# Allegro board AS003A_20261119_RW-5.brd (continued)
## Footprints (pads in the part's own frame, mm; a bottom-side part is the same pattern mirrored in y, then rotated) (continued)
PG_VG93K_PF_DPS32_G8D429
  rect 1.778x1.778 hole 0.711: A1(20.32,3.81) A3(15.24,3.81) A5(10.16,3.81) A7(5.08,3.81) A9(0,3.81) A11(-5.08,3.81) A13(-10.16,3.81) A15(-15.24,3.81) B2(17.78,1.27) B4(12.7,1.27) B6(7.62,1.27) B8(2.54,1.27) B10(-2.54,1.27) B12(-7.62,1.27) B14(-12.7,1.27) B16(-17.78,1.27) C1(20.32,-1.27) C3(15.24,-1.27) C5(10.16,-1.27) C7(5.08,-1.27) C9(0,-1.27) C11(-5.08,-1.27) C13(-10.16,-1.27) C15(-15.24,-1.27) D2(17.78,-3.81) D4(12.7,-3.81) D6(7.62,-3.81) D8(2.54,-3.81) D10(-2.54,-3.81) D12(-7.62,-3.81) D14(-12.7,-3.81) D16(-17.78,-3.81)
  round 1.524 hole 0.711: A2(17.78,3.81) A4(12.7,3.81) A6(7.62,3.81) A8(2.54,3.81) A10(-2.54,3.81) A12(-7.62,3.81) A14(-12.7,3.81) A16(-17.78,3.81) A17(-20.32,3.81) B1(20.32,1.27) B3(15.24,1.27) B5(10.16,1.27) B7(5.08,1.27) B9(0,1.27) B11(-5.08,1.27) B13(-10.16,1.27) B15(-15.24,1.27) B17(-20.32,1.27) C2(17.78,-1.27) C4(12.7,-1.27) C6(7.62,-1.27) C8(2.54,-1.27) C10(-2.54,-1.27) C12(-7.62,-1.27) C14(-12.7,-1.27) C16(-17.78,-1.27) C17(-20.32,-1.27) D1(20.32,-3.81) D3(15.24,-3.81) D5(10.16,-3.81) D7(5.08,-3.81) D9(0,-3.81) D11(-5.08,-3.81) D13(-10.16,-3.81) D15(-15.24,-3.81) D17(-20.32,-3.81)
PG_VG93K_PF_UHC4_G8D230_A34_V2
  round 1.524 hole 0.711: A1(20.325,2.625) A2(18.575,2.625) A3(16.825,2.625) A4(15.075,2.625) B1(20.325,0.875) B2(18.575,0.875) B3(16.825,0.875) B4(15.075,0.875) C1(20.325,-0.875) C2(18.575,-0.875) C3(16.825,-0.875) C4(15.075,-0.875) D1(20.325,-2.625) D2(18.575,-2.625) D3(16.825,-2.625) D4(15.075,-2.625)
  rect 5.6x8.3 smd: G3(10.85,0) G4(-18.95,0)
  round 1.27 hole 0.711: G3_1(13.15,3.5) G3_2(10.85,3.5) G3_3(8.55,3.5) G3_4(12,1.75) G3_5(9.7,1.75) G3_6(13.15,0) G3_7(10.85,0) G3_8(8.55,0) G3_9(12,-1.75) G3_10(9.7,-1.75) G3_11(13.15,-3.5) G3_12(10.85,-3.5) G3_13(8.55,-3.5) G4_1(-16.65,3.5) G4_2(-18.95,3.5) G4_3(-21.25,3.5) G4_4(-17.8,1.75) G4_5(-20.1,1.75) G4_6(-16.65,0) G4_7(-18.95,0) G4_8(-21.25,0) G4_9(-17.8,-1.75) G4_10(-20.1,-1.75) G4_11(-16.65,-3.5) G4_12(-18.95,-3.5) G4_13(-21.25,-3.5) P3_1(6.55,3.5) P3_2(3.35,3.5) P3_3(0.15,3.5) P3_4(-3.05,3.5) P3_5(6.55,0) P3_6(3.35,0) P3_7(0.15,0) P3_8(-3.05,0) P3_9(6.55,-3.5) P3_10(3.35,-3.5) P3_11(0.15,-3.5) P3_12(-3.05,-3.5) P3_13(4.95,1.75) P3_14(1.75,1.75) P3_15(-1.45,1.75) P3_16(4.95,-1.75) P3_17(1.75,-1.75) P3_18(-1.45,-1.75) P4_1(-5.05,3.5) P4_2(-8.25,3.5) P4_3(-11.45,3.5) P4_4(-14.65,3.5) P4_5(-5.05,0) P4_6(-8.25,0) P4_7(-11.45,0) P4_8(-14.65,0) P4_9(-5.05,-3.5) P4_10(-8.25,-3.5) P4_11(-11.45,-3.5) P4_12(-14.65,-3.5) P4_13(-6.65,1.75) P4_14(-9.85,1.75) P4_15(-13.05,1.75) P4_16(-6.65,-1.75) P4_17(-9.85,-1.75) P4_18(-13.05,-1.75)
  rect 10.6x8.3 smd: P3(1.75,0) P4(-9.85,0)
PG_VG93K_PF_UHC4_G8D430_B12_V2
  round 1.524 hole 0.711: A1(20.325,2.625) A2(18.575,2.625) A3(16.825,2.625) A4(15.075,2.625) B1(20.325,0.875) B2(18.575,0.875) B3(16.825,0.875) B4(15.075,0.875) C1(20.325,-0.875) C2(18.575,-0.875) C3(16.825,-0.875) C4(15.075,-0.875) D1(20.325,-2.625) D2(18.575,-2.625) D3(16.825,-2.625) D4(15.075,-2.625)
  rect 5.6x8.3 smd: G1(-18.95,0) G2(10.85,0)
  round 1.27 hole 0.711: G1_1(-16.65,3.5) G1_2(-18.95,3.5) G1_3(-21.25,3.5) G1_4(-17.8,1.75) G1_5(-20.1,1.75) G1_6(-16.65,0) G1_7(-18.95,0) G1_8(-21.25,0) G1_9(-17.8,-1.75) G1_10(-20.1,-1.75) G1_11(-16.65,-3.5) G1_12(-18.95,-3.5) G1_13(-21.25,-3.5) G2_1(13.15,3.5) G2_2(10.85,3.5) G2_3(8.55,3.5) G2_4(12,1.75) G2_5(9.7,1.75) G2_6(13.15,0) G2_7(10.85,0) G2_8(8.55,0) G2_9(12,-1.75) G2_10(9.7,-1.75) G2_11(13.15,-3.5) G2_12(10.85,-3.5) G2_13(8.55,-3.5) P1_1(-5.05,3.5) P1_2(-8.25,3.5) P1_3(-11.45,3.5) P1_4(-14.65,3.5) P1_5(-5.05,0) P1_6(-8.25,0) P1_7(-11.45,0) P1_8(-14.65,0) P1_9(-5.05,-3.5) P1_10(-8.25,-3.5) P1_11(-11.45,-3.5) P1_12(-14.65,-3.5) P1_13(-6.65,1.75) P1_14(-9.85,1.75) P1_15(-13.05,1.75) P1_16(-6.65,-1.75) P1_17(-9.85,-1.75) P1_18(-13.05,-1.75) P2_1(6.55,3.5) P2_2(3.35,3.5) P2_3(0.15,3.5) P2_4(-3.05,3.5) P2_5(6.55,0) P2_6(3.35,0) P2_7(0.15,0) P2_8(-3.05,0) P2_9(6.55,-3.5) P2_10(3.35,-3.5) P2_11(0.15,-3.5) P2_12(-3.05,-3.5) P2_13(4.95,1.75) P2_14(1.75,1.75) P2_15(-1.45,1.75) P2_16(4.95,-1.75) P2_17(1.75,-1.75) P2_18(-1.45,-1.75)
  rect 10.6x8.3 smd: P1(-9.85,0) P2(1.75,0)
R0201
  rect 0.305x0.356 smd: 1(-0.3,0) 2(0.3,0)
R0402
  custom 0.15x0.15 smd: 1(-0.5,0) 2(0.5,0)
R0402_UNBGA_V2
  rect 0.508x0.508 smd: 1(-0.425,0) 2(0.425,0)
R0603
  rect 0.889x0.889 smd: 1(-0.85,0) 2(0.85,0)
R0805
  rect 1.118x1.372 smd: 1(-0.95,0) 2(0.95,0)
R1206
  rect 1.321x1.829 smd: 1(-1.25,0) 2(1.25,0)
RL_712D_5V_V2
  round 1.397 hole 1.041: 1(1.493,-2.055) 2(2.416,-0.785) 3(2.416,0.785) 4(1.493,2.055) 6(-1.493,2.055) 7(-2.416,0.785) 8(-2.416,-0.785) 9(-1.493,-2.055)
RL_COTO2911_5V_RLPIN
  rect 1.88x1.88 hole 1.372: 1(17.78,0)
  round 0.051 smd: 2(15.24,0)
  round 1.88 hole 1.372: 3(2.54,0) 4(0,0) 5(0,-2.54) 6(2.54,-2.54) 7(15.24,-2.54) 8(17.78,-2.54)
RL_NECUA2_5V_V3
  rect 1.626x1.626 hole 1.041: 1(3.6,1.6)
  round 1.626 hole 1.041: 2(0.4,1.6) 3(-1.8,1.6) 4(-4,1.6) 5(-4,-1.6) 6(-1.8,-1.6) 7(0.4,-1.6) 8(3.6,-1.6)
RL_SGRF303_5V
  oval 3.429x0.559 smd rot 54: 1(2.344,-3.226) 6(-2.344,3.226)
  oval 3.429x0.559 smd rot 18: 2(3.793,-1.232) 7(-3.793,1.232)
  oval 3.429x0.559 smd rot 162: 3(3.793,1.232) 8(-3.793,-1.232)
  oval 3.429x0.559 smd rot 126: 4(2.344,3.226) 9(-2.344,-3.226)
  custom 2.5x2.5 smd: G1(0,0)
  round 1.397 hole 1.041: G2(0,-2.54) G3(0,2.54)
SK_BGA1024P_0P8MM_WW_71117890
  round 0.508 hole 1.61 unplated: (-17.5,17.5) (-17.5,-17.5) (17.5,17.5) (17.5,-17.5)
  round 0.6 smd: A1(-12.4,12.4) A2(-11.6,12.4) A3(-10.8,12.4) A4(-10,12.4) A5(-9.2,12.4) A6(-8.4,12.4) A7(-7.6,12.4) A8(-6.8,12.4) A9(-6,12.4) A10(-5.2,12.4) A11(-4.4,12.4) A12(-3.6,12.4) A13(-2.8,12.4) A14(-2,12.4) A15(-1.2,12.4) A16(-0.4,12.4) A17(0.4,12.4) A18(1.2,12.4) A19(2,12.4) A20(2.8,12.4) A21(3.6,12.4) A22(4.4,12.4) A23(5.2,12.4) A24(6,12.4) A25(6.8,12.4) A26(7.6,12.4) A27(8.4,12.4) A28(9.2,12.4) A29(10,12.4) A30(10.8,12.4) A31(11.6,12.4) A32(12.4,12.4) AA1(-12.4,-3.6) AA2(-11.6,-3.6) AA3(-10.8,-3.6) AA4(-10,-3.6) AA5(-9.2,-3.6) AA6(-8.4,-3.6) AA7(-7.6,-3.6) AA8(-6.8,-3.6) AA9(-6,-3.6) AA10(-5.2,-3.6) AA11(-4.4,-3.6) AA12(-3.6,-3.6) AA13(-2.8,-3.6) AA14(-2,-3.6) AA15(-1.2,-3.6) AA16(-0.4,-3.6) AA17(0.4,-3.6) AA18(1.2,-3.6) AA19(2,-3.6) AA20(2.8,-3.6) AA21(3.6,-3.6) AA22(4.4,-3.6) AA23(5.2,-3.6) AA24(6,-3.6) AA25(6.8,-3.6) AA26(7.6,-3.6) AA27(8.4,-3.6) AA28(9.2,-3.6) AA29(10,-3.6) AA30(10.8,-3.6) AA31(11.6,-3.6) AA32(12.4,-3.6) AB1(-12.4,-4.4) AB2(-11.6,-4.4) AB3(-10.8,-4.4) AB4(-10,-4.4) AB5(-9.2,-4.4) AB6(-8.4,-4.4) AB7(-7.6,-4.4) AB8(-6.8,-4.4) AB9(-6,-4.4) AB10(-5.2,-4.4) AB11(-4.4,-4.4) AB12(-3.6,-4.4) AB13(-2.8,-4.4) AB14(-2,-4.4) AB15(-1.2,-4.4) AB16(-0.4,-4.4) AB17(0.4,-4.4) AB18(1.2,-4.4) AB19(2,-4.4) AB20(2.8,-4.4) AB21(3.6,-4.4) AB22(4.4,-4.4) AB23(5.2,-4.4) AB24(6,-4.4) AB25(6.8,-4.4) AB26(7.6,-4.4) AB27(8.4,-4.4) AB28(9.2,-4.4) AB29(10,-4.4) AB30(10.8,-4.4) AB31(11.6,-4.4) AB32(12.4,-4.4) AC1(-12.4,-5.2) AC2(-11.6,-5.2) AC3(-10.8,-5.2) AC4(-10,-5.2) AC5(-9.2,-5.2) AC6(-8.4,-5.2) AC7(-7.6,-5.2) AC8(-6.8,-5.2) AC9(-6,-5.2) AC10(-5.2,-5.2) AC11(-4.4,-5.2) AC12(-3.6,-5.2) AC13(-2.8,-5.2) AC14(-2,-5.2) AC15(-1.2,-5.2) AC16(-0.4,-5.2) AC17(0.4,-5.2) AC18(1.2,-5.2) AC19(2,-5.2) AC20(2.8,-5.2) AC21(3.6,-5.2) AC22(4.4,-5.2) AC23(5.2,-5.2) AC24(6,-5.2) AC25(6.8,-5.2) AC26(7.6,-5.2) AC27(8.4,-5.2) AC28(9.2,-5.2) AC29(10,-5.2) AC30(10.8,-5.2) AC31(11.6,-5.2) AC32(12.4,-5.2) AD1(-12.4,-6) AD2(-11.6,-6) AD3(-10.8,-6) AD4(-10,-6) AD5(-9.2,-6) AD6(-8.4,-6) AD7(-7.6,-6) AD8(-6.8,-6) AD9(-6,-6) AD10(-5.2,-6) AD11(-4.4,-6) AD12(-3.6,-6) AD13(-2.8,-6) AD14(-2,-6) AD15(-1.2,-6) AD16(-0.4,-6) AD17(0.4,-6) AD18(1.2,-6) AD19(2,-6) AD20(2.8,-6) AD21(3.6,-6) AD22(4.4,-6) AD23(5.2,-6) AD24(6,-6) AD25(6.8,-6) AD26(7.6,-6) AD27(8.4,-6) AD28(9.2,-6) AD29(10,-6) AD30(10.8,-6) AD31(11.6,-6) AD32(12.4,-6) AE1(-12.4,-6.8) AE2(-11.6,-6.8) AE3(-10.8,-6.8) AE4(-10,-6.8) AE5(-9.2,-6.8) AE6(-8.4,-6.8) AE7(-7.6,-6.8) AE8(-6.8,-6.8) AE9(-6,-6.8) AE10(-5.2,-6.8) AE11(-4.4,-6.8) AE12(-3.6,-6.8) AE13(-2.8,-6.8) AE14(-2,-6.8) AE15(-1.2,-6.8) AE16(-0.4,-6.8) AE17(0.4,-6.8) AE18(1.2,-6.8) AE19(2,-6.8) AE20(2.8,-6.8) AE21(3.6,-6.8) AE22(4.4,-6.8) AE23(5.2,-6.8) AE24(6,-6.8) AE25(6.8,-6.8) AE26(7.6,-6.8) AE27(8.4,-6.8) AE28(9.2,-6.8) AE29(10,-6.8) AE30(10.8,-6.8) AE31(11.6,-6.8) AE32(12.4,-6.8) AF1(-12.4,-7.6) AF2(-11.6,-7.6) AF3(-10.8,-7.6) AF4(-10,-7.6) AF5(-9.2,-7.6) AF6(-8.4,-7.6) AF7(-7.6,-7.6) AF8(-6.8,-7.6) AF9(-6,-7.6) AF10(-5.2,-7.6) AF11(-4.4,-7.6) AF12(-3.6,-7.6) AF13(-2.8,-7.6) AF14(-2,-7.6) AF15(-1.2,-7.6) AF16(-0.4,-7.6) AF17(0.4,-7.6) AF18(1.2,-7.6) AF19(2,-7.6) AF20(2.8,-7.6) AF21(3.6,-7.6) AF22(4.4,-7.6) AF23(5.2,-7.6) AF24(6,-7.6) AF25(6.8,-7.6) AF26(7.6,-7.6) AF27(8.4,-7.6) AF28(9.2,-7.6) AF29(10,-7.6) AF30(10.8,-7.6) AF31(11.6,-7.6) AF32(12.4,-7.6) AG1(-12.4,-8.4) AG2(-11.6,-8.4) AG3(-10.8,-8.4) AG4(-10,-8.4) AG5(-9.2,-8.4) AG6(-8.4,-8.4) AG7(-7.6,-8.4) AG8(-6.8,-8.4) AG9(-6,-8.4) AG10(-5.2,-8.4) AG11(-4.4,-8.4) AG12(-3.6,-8.4) AG13(-2.8,-8.4) AG14(-2,-8.4) AG15(-1.2,-8.4) AG16(-0.4,-8.4) AG17(0.4,-8.4) AG18(1.2,-8.4) AG19(2,-8.4) AG20(2.8,-8.4) AG21(3.6,-8.4) AG22(4.4,-8.4) AG23(5.2,-8.4) AG24(6,-8.4) AG25(6.8,-8.4) AG26(7.6,-8.4) AG27(8.4,-8.4) AG28(9.2,-8.4) AG29(10,-8.4) AG30(10.8,-8.4) AG31(11.6,-8.4) AG32(12.4,-8.4) AH1(-12.4,-9.2) AH2(-11.6,-9.2) AH3(-10.8,-9.2) AH4(-10,-9.2) AH5(-9.2,-9.2) AH6(-8.4,-9.2) AH7(-7.6,-9.2) AH8(-6.8,-9.2) AH9(-6,-9.2) AH10(-5.2,-9.2) AH11(-4.4,-9.2) AH12(-3.6,-9.2) AH13(-2.8,-9.2) AH14(-2,-9.2) AH15(-1.2,-9.2) AH16(-0.4,-9.2) AH17(0.4,-9.2) AH18(1.2,-9.2) AH19(2,-9.2) AH20(2.8,-9.2) AH21(3.6,-9.2) AH22(4.4,-9.2) AH23(5.2,-9.2) AH24(6,-9.2) AH25(6.8,-9.2) AH26(7.6,-9.2) AH27(8.4,-9.2) AH28(9.2,-9.2) AH29(10,-9.2) AH30(10.8,-9.2) AH31(11.6,-9.2) AH32(12.4,-9.2) AJ1(-12.4,-10) AJ2(-11.6,-10) AJ3(-10.8,-10) AJ4(-10,-10) AJ5(-9.2,-10) AJ6(-8.4,-10) AJ7(-7.6,-10) AJ8(-6.8,-10) AJ9(-6,-10) AJ10(-5.2,-10) AJ11(-4.4,-10) AJ12(-3.6,-10) AJ13(-2.8,-10) AJ14(-2,-10) AJ15(-1.2,-10) AJ16(-0.4,-10) AJ17(0.4,-10) AJ18(1.2,-10) AJ19(2,-10) AJ20(2.8,-10) AJ21(3.6,-10) AJ22(4.4,-10) AJ23(5.2,-10) AJ24(6,-10) AJ25(6.8,-10) AJ26(7.6,-10) AJ27(8.4,-10) AJ28(9.2,-10) AJ29(10,-10) AJ30(10.8,-10) AJ31(11.6,-10) AJ32(12.4,-10) AK1(-12.4,-10.8) AK2(-11.6,-10.8) AK3(-10.8,-10.8) AK4(-10,-10.8) AK5(-9.2,-10.8) AK6(-8.4,-10.8) AK7(-7.6,-10.8) AK8(-6.8,-10.8) AK9(-6,-10.8) AK10(-5.2,-10.8) AK11(-4.4,-10.8) AK12(-3.6,-10.8) AK13(-2.8,-10.8) AK14(-2,-10.8) AK15(-1.2,-10.8) AK16(-0.4,-10.8) AK17(0.4,-10.8) AK18(1.2,-10.8) AK19(2,-10.8) AK20(2.8,-10.8) AK21(3.6,-10.8) AK22(4.4,-10.8) AK23(5.2,-10.8) AK24(6,-10.8) AK25(6.8,-10.8) AK26(7.6,-10.8) AK27(8.4,-10.8) AK28(9.2,-10.8) AK29(10,-10.8) AK30(10.8,-10.8) AK31(11.6,-10.8) AK32(12.4,-10.8) AL1(-12.4,-11.6) AL2(-11.6,-11.6) AL3(-10.8,-11.6) AL4(-10,-11.6) AL5(-9.2,-11.6) AL6(-8.4,-11.6) AL7(-7.6,-11.6) AL8(-6.8,-11.6) AL9(-6,-11.6) AL10(-5.2,-11.6) AL11(-4.4,-11.6) AL12(-3.6,-11.6) AL13(-2.8,-11.6) AL14(-2,-11.6) AL15(-1.2,-11.6) AL16(-0.4,-11.6) AL17(0.4,-11.6) AL18(1.2,-11.6) AL19(2,-11.6) AL20(2.8,-11.6) AL21(3.6,-11.6) AL22(4.4,-11.6) AL23(5.2,-11.6) AL24(6,-11.6) AL25(6.8,-11.6) AL26(7.6,-11.6) AL27(8.4,-11.6) AL28(9.2,-11.6) AL29(10,-11.6) AL30(10.8,-11.6) AL31(11.6,-11.6) AL32(12.4,-11.6) AM1(-12.4,-12.4) AM2(-11.6,-12.4) AM3(-10.8,-12.4) AM4(-10,-12.4) AM5(-9.2,-12.4) AM6(-8.4,-12.4) AM7(-7.6,-12.4) AM8(-6.8,-12.4) AM9(-6,-12.4) AM10(-5.2,-12.4) AM11(-4.4,-12.4) AM12(-3.6,-12.4) AM13(-2.8,-12.4) AM14(-2,-12.4) AM15(-1.2,-12.4) AM16(-0.4,-12.4) AM17(0.4,-12.4) AM18(1.2,-12.4) AM19(2,-12.4) AM20(2.8,-12.4) AM21(3.6,-12.4) AM22(4.4,-12.4) AM23(5.2,-12.4) AM24(6,-12.4) AM25(6.8,-12.4) AM26(7.6,-12.4) AM27(8.4,-12.4) AM28(9.2,-12.4) AM29(10,-12.4) AM30(10.8,-12.4) AM31(11.6,-12.4) AM32(12.4,-12.4) B1(-12.4,11.6) B2(-11.6,11.6) B3(-10.8,11.6) B4(-10,11.6) B5(-9.2,11.6) B6(-8.4,11.6) B7(-7.6,11.6) B8(-6.8,11.6) B9(-6,11.6) B10(-5.2,11.6) B11(-4.4,11.6) B12(-3.6,11.6) B13(-2.8,11.6) B14(-2,11.6) B15(-1.2,11.6) B16(-0.4,11.6) B17(0.4,11.6) B18(1.2,11.6) B19(2,11.6) B20(2.8,11.6) B21(3.6,11.6) B22(4.4,11.6) B23(5.2,11.6) B24(6,11.6) B25(6.8,11.6) B26(7.6,11.6) B27(8.4,11.6) B28(9.2,11.6) B29(10,11.6) B30(10.8,11.6) B31(11.6,11.6) B32(12.4,11.6) C1(-12.4,10.8) C2(-11.6,10.8) C3(-10.8,10.8) C4(-10,10.8) C5(-9.2,10.8) C6(-8.4,10.8) C7(-7.6,10.8) C8(-6.8,10.8) C9(-6,10.8) C10(-5.2,10.8) C11(-4.4,10.8) C12(-3.6,10.8) C13(-2.8,10.8) C14(-2,10.8) C15(-1.2,10.8) C16(-0.4,10.8) C17(0.4,10.8) C18(1.2,10.8) C19(2,10.8) C20(2.8,10.8) C21(3.6,10.8) C22(4.4,10.8) C23(5.2,10.8) C24(6,10.8) C25(6.8,10.8) C26(7.6,10.8) C27(8.4,10.8) C28(9.2,10.8) C29(10,10.8) C30(10.8,10.8) C31(11.6,10.8) C32(12.4,10.8) D1(-12.4,10) D2(-11.6,10) D3(-10.8,10) D4(-10,10) D5(-9.2,10) D6(-8.4,10) D7(-7.6,10) D8(-6.8,10) D9(-6,10) D10(-5.2,10) D11(-4.4,10) D12(-3.6,10) D13(-2.8,10) D14(-2,10) D15(-1.2,10) D16(-0.4,10) D17(0.4,10) D18(1.2,10) D19(2,10) D20(2.8,10) D21(3.6,10) D22(4.4,10) D23(5.2,10) D24(6,10) D25(6.8,10) D26(7.6,10) D27(8.4,10) D28(9.2,10) D29(10,10) D30(10.8,10) D31(11.6,10) D32(12.4,10) E1(-12.4,9.2) E2(-11.6,9.2) E3(-10.8,9.2) E4(-10,9.2) E5(-9.2,9.2) E6(-8.4,9.2) E7(-7.6,9.2) E8(-6.8,9.2) E9(-6,9.2) E10(-5.2,9.2) E11(-4.4,9.2) E12(-3.6,9.2) E13(-2.8,9.2) E14(-2,9.2) E15(-1.2,9.2) E16(-0.4,9.2) E17(0.4,9.2) E18(1.2,9.2) E19(2,9.2) E20(2.8,9.2) E21(3.6,9.2) E22(4.4,9.2) E23(5.2,9.2) E24(6,9.2) E25(6.8,9.2) E26(7.6,9.2) E27(8.4,9.2) E28(9.2,9.2) E29(10,9.2) E30(10.8,9.2) E31(11.6,9.2) E32(12.4,9.2) F1(-12.4,8.4) F2(-11.6,8.4) F3(-10.8,8.4) F4(-10,8.4) F5(-9.2,8.4) F6(-8.4,8.4) F7(-7.6,8.4) F8(-6.8,8.4) F9(-6,8.4) F10(-5.2,8.4) F11(-4.4,8.4) F12(-3.6,8.4) F13(-2.8,8.4) F14(-2,8.4) F15(-1.2,8.4) F16(-0.4,8.4) F17(0.4,8.4) F18(1.2,8.4) F19(2,8.4) F20(2.8,8.4) F21(3.6,8.4) F22(4.4,8.4) F23(5.2,8.4) F24(6,8.4) F25(6.8,8.4) F26(7.6,8.4) F27(8.4,8.4) F28(9.2,8.4) F29(10,8.4) F30(10.8,8.4) F31(11.6,8.4) F32(12.4,8.4) G1(-12.4,7.6) G2(-11.6,7.6) G3(-10.8,7.6) G4(-10,7.6) G5(-9.2,7.6) G6(-8.4,7.6) G7(-7.6,7.6) G8(-6.8,7.6) G9(-6,7.6) G10(-5.2,7.6) G11(-4.4,7.6) G12(-3.6,7.6) G13(-2.8,7.6) G14(-2,7.6) G15(-1.2,7.6) G16(-0.4,7.6) G17(0.4,7.6) G18(1.2,7.6) G19(2,7.6) G20(2.8,7.6) G21(3.6,7.6) G22(4.4,7.6) G23(5.2,7.6) G24(6,7.6) G25(6.8,7.6) G26(7.6,7.6) G27(8.4,7.6) G28(9.2,7.6) G29(10,7.6) G30(10.8,7.6) G31(11.6,7.6) G32(12.4,7.6) H1(-12.4,6.8) H2(-11.6,6.8) H3(-10.8,6.8) H4(-10,6.8) H5(-9.2,6.8) H6(-8.4,6.8) H7(-7.6,6.8) H8(-6.8,6.8) H9(-6,6.8) H10(-5.2,6.8) H11(-4.4,6.8) H12(-3.6,6.8) H13(-2.8,6.8) H14(-2,6.8) H15(-1.2,6.8) H16(-0.4,6.8) H17(0.4,6.8) H18(1.2,6.8) H19(2,6.8) H20(2.8,6.8) H21(3.6,6.8) H22(4.4,6.8) H23(5.2,6.8) H24(6,6.8) H25(6.8,6.8) H26(7.6,6.8) H27(8.4,6.8) H28(9.2,6.8) H29(10,6.8) H30(10.8,6.8) H31(11.6,6.8) H32(12.4,6.8) J1(-12.4,6) J2(-11.6,6) J3(-10.8,6) J4(-10,6) J5(-9.2,6) J6(-8.4,6) J7(-7.6,6) J8(-6.8,6) J9(-6,6) J10(-5.2,6) J11(-4.4,6) J12(-3.6,6) J13(-2.8,6) J14(-2,6) J15(-1.2,6) J16(-0.4,6) J17(0.4,6) J18(1.2,6) J19(2,6) J20(2.8,6) J21(3.6,6) J22(4.4,6) J23(5.2,6) J24(6,6) J25(6.8,6) J26(7.6,6) J27(8.4,6) J28(9.2,6) J29(10,6) J30(10.8,6) J31(11.6,6) J32(12.4,6) K1(-12.4,5.2) K2(-11.6,5.2) K3(-10.8,5.2) K4(-10,5.2) K5(-9.2,5.2) K6(-8.4,5.2) K7(-7.6,5.2) K8(-6.8,5.2) K9(-6,5.2) K10(-5.2,5.2) K11(-4.4,5.2) K12(-3.6,5.2) K13(-2.8,5.2) K14(-2,5.2) K15(-1.2,5.2) K16(-0.4,5.2) K17(0.4,5.2) K18(1.2,5.2) K19(2,5.2) K20(2.8,5.2) K21(3.6,5.2) K22(4.4,5.2) K23(5.2,5.2) K24(6,5.2) K25(6.8,5.2) K26(7.6,5.2) K27(8.4,5.2) K28(9.2,5.2) K29(10,5.2) K30(10.8,5.2) K31(11.6,5.2) K32(12.4,5.2) L1(-12.4,4.4) L2(-11.6,4.4) L3(-10.8,4.4) L4(-10,4.4) L5(-9.2,4.4) L6(-8.4,4.4) L7(-7.6,4.4) L8(-6.8,4.4) L9(-6,4.4) L10(-5.2,4.4) L11(-4.4,4.4) L12(-3.6,4.4) L13(-2.8,4.4) L14(-2,4.4) L15(-1.2,4.4) L16(-0.4,4.4) L17(0.4,4.4) L18(1.2,4.4) L19(2,4.4) L20(2.8,4.4) L21(3.6,4.4) L22(4.4,4.4) L23(5.2,4.4) L24(6,4.4) L25(6.8,4.4) L26(7.6,4.4) L27(8.4,4.4) L28(9.2,4.4) L29(10,4.4) L30(10.8,4.4) L31(11.6,4.4) L32(12.4,4.4) M1(-12.4,3.6) M2(-11.6,3.6) M3(-10.8,3.6) M4(-10,3.6) M5(-9.2,3.6) M6(-8.4,3.6) M7(-7.6,3.6) M8(-6.8,3.6) M9(-6,3.6) M10(-5.2,3.6) M11(-4.4,3.6) M12(-3.6,3.6) M13(-2.8,3.6) M14(-2,3.6) M15(-1.2,3.6) M16(-0.4,3.6) M17(0.4,3.6) M18(1.2,3.6) M19(2,3.6) M20(2.8,3.6) M21(3.6,3.6) M22(4.4,3.6) M23(5.2,3.6) M24(6,3.6) M25(6.8,3.6) M26(7.6,3.6) M27(8.4,3.6) M28(9.2,3.6) M29(10,3.6) M30(10.8,3.6) M31(11.6,3.6) M32(12.4,3.6) N1(-12.4,2.8) N2(-11.6,2.8) N3(-10.8,2.8) N4(-10,2.8) N5(-9.2,2.8) N6(-8.4,2.8) N7(-7.6,2.8) N8(-6.8,2.8) N9(-6,2.8) N10(-5.2,2.8) N11(-4.4,2.8) N12(-3.6,2.8) N13(-2.8,2.8) N14(-2,2.8) N15(-1.2,2.8) N16(-0.4,2.8) N17(0.4,2.8) N18(1.2,2.8) N19(2,2.8) N20(2.8,2.8) N21(3.6,2.8) N22(4.4,2.8) N23(5.2,2.8) N24(6,2.8) N25(6.8,2.8) N26(7.6,2.8) N27(8.4,2.8) N28(9.2,2.8) N29(10,2.8) N30(10.8,2.8) N31(11.6,2.8) N32(12.4,2.8) P1(-12.4,2) P2(-11.6,2) P3(-10.8,2) P4(-10,2) P5(-9.2,2) P6(-8.4,2) P7(-7.6,2) P8(-6.8,2) P9(-6,2) P10(-5.2,2) P11(-4.4,2) P12(-3.6,2) P13(-2.8,2) P14(-2,2) P15(-1.2,2) P16(-0.4,2) P17(0.4,2) P18(1.2,2) P19(2,2) P20(2.8,2) P21(3.6,2) P22(4.4,2) P23(5.2,2) P24(6,2) P25(6.8,2) P26(7.6,2) P27(8.4,2) P28(9.2,2) P29(10,2) P30(10.8,2) P31(11.6,2) P32(12.4,2) R1(-12.4,1.2) R2(-11.6,1.2) R3(-10.8,1.2) R4(-10,1.2) R5(-9.2,1.2) R6(-8.4,1.2) R7(-7.6,1.2) R8(-6.8,1.2) R9(-6,1.2) R10(-5.2,1.2) R11(-4.4,1.2) R12(-3.6,1.2) R13(-2.8,1.2) R14(-2,1.2) R15(-1.2,1.2) R16(-0.4,1.2) R17(0.4,1.2) R18(1.2,1.2) R19(2,1.2) R20(2.8,1.2) R21(3.6,1.2) R22(4.4,1.2) R23(5.2,1.2) R24(6,1.2) R25(6.8,1.2) R26(7.6,1.2) R27(8.4,1.2) R28(9.2,1.2) R29(10,1.2) R30(10.8,1.2) R31(11.6,1.2) R32(12.4,1.2) T1(-12.4,0.4) T2(-11.6,0.4) T3(-10.8,0.4) T4(-10,0.4) T5(-9.2,0.4) T6(-8.4,0.4) T7(-7.6,0.4) T8(-6.8,0.4) T9(-6,0.4) T10(-5.2,0.4) T11(-4.4,0.4) T12(-3.6,0.4) T13(-2.8,0.4) T14(-2,0.4) T15(-1.2,0.4) T16(-0.4,0.4) T17(0.4,0.4) T18(1.2,0.4) T19(2,0.4) T20(2.8,0.4) T21(3.6,0.4) T22(4.4,0.4) T23(5.2,0.4) T24(6,0.4) T25(6.8,0.4) T26(7.6,0.4) T27(8.4,0.4) T28(9.2,0.4) T29(10,0.4) T30(10.8,0.4) T31(11.6,0.4) T32(12.4,0.4) U1(-12.4,-0.4) U2(-11.6,-0.4) U3(-10.8,-0.4) U4(-10,-0.4) U5(-9.2,-0.4) U6(-8.4,-0.4) U7(-7.6,-0.4) U8(-6.8,-0.4) U9(-6,-0.4) U10(-5.2,-0.4) U11(-4.4,-0.4) U12(-3.6,-0.4) U13(-2.8,-0.4) U14(-2,-0.4) U15(-1.2,-0.4) U16(-0.4,-0.4) U17(0.4,-0.4) U18(1.2,-0.4) U19(2,-0.4) U20(2.8,-0.4) U21(3.6,-0.4) U22(4.4,-0.4) U23(5.2,-0.4) U24(6,-0.4) U25(6.8,-0.4) U26(7.6,-0.4) U27(8.4,-0.4) U28(9.2,-0.4) U29(10,-0.4) U30(10.8,-0.4) U31(11.6,-0.4) U32(12.4,-0.4) V1(-12.4,-1.2) V2(-11.6,-1.2) V3(-10.8,-1.2) V4(-10,-1.2) V5(-9.2,-1.2) V6(-8.4,-1.2) V7(-7.6,-1.2) V8(-6.8,-1.2) V9(-6,-1.2) V10(-5.2,-1.2) V11(-4.4,-1.2) V12(-3.6,-1.2) V13(-2.8,-1.2) V14(-2,-1.2) V15(-1.2,-1.2) V16(-0.4,-1.2) V17(0.4,-1.2) V18(1.2,-1.2) V19(2,-1.2) V20(2.8,-1.2) V21(3.6,-1.2) V22(4.4,-1.2) V23(5.2,-1.2) V24(6,-1.2) V25(6.8,-1.2) V26(7.6,-1.2) V27(8.4,-1.2) V28(9.2,-1.2) V29(10,-1.2) V30(10.8,-1.2) V31(11.6,-1.2) V32(12.4,-1.2) W1(-12.4,-2) W2(-11.6,-2) W3(-10.8,-2) W4(-10,-2) W5(-9.2,-2) W6(-8.4,-2) W7(-7.6,-2) W8(-6.8,-2) W9(-6,-2) W10(-5.2,-2) W11(-4.4,-2) W12(-3.6,-2) W13(-2.8,-2) W14(-2,-2) W15(-1.2,-2) W16(-0.4,-2) W17(0.4,-2) W18(1.2,-2) W19(2,-2) W20(2.8,-2) W21(3.6,-2) W22(4.4,-2) W23(5.2,-2) W24(6,-2) W25(6.8,-2) W26(7.6,-2) W27(8.4,-2) W28(9.2,-2) W29(10,-2) W30(10.8,-2) W31(11.6,-2) W32(12.4,-2) Y1(-12.4,-2.8) Y2(-11.6,-2.8) Y3(-10.8,-2.8) Y4(-10,-2.8) Y5(-9.2,-2.8) Y6(-8.4,-2.8) Y7(-7.6,-2.8) Y8(-6.8,-2.8) Y9(-6,-2.8) Y10(-5.2,-2.8) Y11(-4.4,-2.8) Y12(-3.6,-2.8) Y13(-2.8,-2.8) Y14(-2,-2.8) Y15(-1.2,-2.8) Y16(-0.4,-2.8) Y17(0.4,-2.8) Y18(1.2,-2.8) Y19(2,-2.8) Y20(2.8,-2.8) Y21(3.6,-2.8) Y22(4.4,-2.8) Y23(5.2,-2.8) Y24(6,-2.8) Y25(6.8,-2.8) Y26(7.6,-2.8) Y27(8.4,-2.8) Y28(9.2,-2.8) Y29(10,-2.8) Y30(10.8,-2.8) Y31(11.6,-2.8) Y32(12.4,-2.8)
  round 6.502 hole 4.293: NUT1(-21,21) NUT2(21,21) NUT3(-21,-21) NUT4(21,-21)
SMA_32K10K_400L5_5P_V2
  round 1.27 smd: 1(0,0)
  round 2.286 hole 1.499: 2(-2.54,2.54) 3(-2.54,-2.54) 4(2.54,-2.54) 5(2.54,2.54)
SO8_215X127MM
  rect 1.778x0.762 smd: 1(-2.731,2.032) 4(-2.731,-2.032) 5(2.731,-2.032) 8(2.731,2.032)
  rect 1.778x0.61 smd: 2(-2.731,0.635) 3(-2.731,-0.635) 6(2.731,-0.635) 7(2.731,0.635)
SOCKET_CODE
  round 0.051 smd: 1(0,0)
TP_040_T
  round 1.016 smd: 1(0,0)
TP_060_040
  round 1.524 hole 1.016: 1(0,0)
unnamed#2
  round 1.016 smd: 1(0,0)
V93K_TOUCHSENSOR_FY
  round 0.051 smd: 1(0,0)
VQFN3X3_20P_0P4MM_EP_TI
  rect 0.7x0.25 smd: 1(-1.45,0.8) 2(-1.45,0.4) 3(-1.45,0) 4(-1.45,-0.4) 5(-1.45,-0.8) 11(1.45,-0.8) 12(1.45,-0.4) 13(1.45,0) 14(1.45,0.4) 15(1.45,0.8)
  rect 0.25x0.7 smd: 6(-0.8,-1.45) 7(-0.4,-1.45) 8(0,-1.45) 9(0.4,-1.45) 10(0.8,-1.45) 16(0.8,1.45) 17(0.4,1.45) 18(0,1.45) 19(-0.4,1.45) 20(-0.8,1.45)
  rect 1.7x1.7 smd: EPAD(0,0)

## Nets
